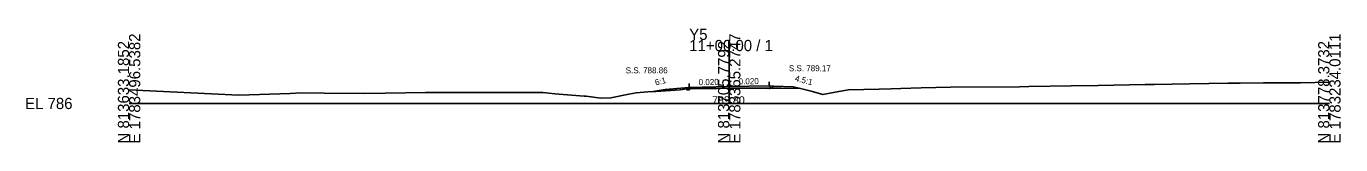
# Model space of a CAD drawing. Extents: x -26 to 1603, y -10 to 6526.
# Drawn here: x -25.7 to 302.8, y 1490.3 to 1518.7 of the extents above; entities that cross this region are included whole.
import ezdxf

# ---------------------------------------------------------------- set-up
doc = ezdxf.new("R2010")
doc.units = 0
for name, color, linetype in [('Exist Cross Section Cell', 7, 'Continuous'), ('Exist XS Center Line Elevation Label', 7, 'Continuous'), ('Exist XS Ground Line', 7, 'Continuous'), ('Prop XS Dump Level', 7, 'Continuous'), ('Prop XS Earthwork Shape', 7, 'Continuous'), ('Prop XS EOT Tick Mark', 7, 'Continuous'), ('Prop XS Finish Grade', 7, 'Continuous'), ('Prop XS Finish Grade Earthwork', 7, 'Continuous'), ('Prop XS Finish Grade Pavement', 7, 'Continuous'), ('Prop XS Pvmt Edge Slope', 7, 'Continuous'), ('Prop XS SE Text', 7, 'Continuous'), ('Prop XS Side Slope Text', 7, 'Continuous'), ('Prop XS SS Elevation Text', 7, 'Continuous'), ('Prop XS Subgrade Earthwork', 7, 'Continuous')]:
    doc.layers.add(name, color=color, linetype=linetype)

msp = doc.modelspace()

# ---------------------------------------------------------------- linework, layer by layer
at = {"layer": 'Exist Cross Section Cell'}
for p, q in [((150, 1500), (150, 1515.87)), ((0, 1500), (150, 1500)), ((150, 1500), (300, 1500))]:
    msp.add_line(p, q, dxfattribs=at)
at = {"layer": 'Exist XS Ground Line'}
for p, q in [((242.2, 1504.49), (253.93, 1504.73)), ((253.93, 1504.73), (256.25, 1504.77)), ((256.25, 1504.77), (265.03, 1504.9)), ((265.03, 1504.9), (274.7, 1505.08)), ((274.7, 1505.08), (277.69, 1505.08)), ((277.69, 1505.08), (283.57, 1505.13)), ((283.57, 1505.13), (292.81, 1505.19)), ((292.81, 1505.19), (300, 1505.29)), ((0, 1503.43), (27.43, 1502.11)), ((27.43, 1502.11), (40.23, 1502.53)), ((40.23, 1502.53), (43.04, 1502.62)), ((43.04, 1502.62), (48.73, 1502.57)), ((48.73, 1502.57), (58.62, 1502.5)), ((58.62, 1502.5), (64.04, 1502.59)), ((64.04, 1502.59), (74.09, 1502.72)), ((74.09, 1502.72), (83.9, 1502.73)), ((83.9, 1502.73), (89.5, 1502.72)), ((89.5, 1502.72), (91.24, 1502.7)), ((91.24, 1502.7), (103.45, 1502.75)), ((103.45, 1502.75), (106.4, 1502.4)), ((106.4, 1502.4), (113.73, 1501.86)), ((113.73, 1501.86), (114.22, 1501.82)), ((114.22, 1501.82), (117.9, 1501.35)), ((117.9, 1501.35), (120.45, 1501.42)), ((120.45, 1501.42), (124.93, 1502.32)), ((124.93, 1502.32), (126.77, 1502.68)), ((126.77, 1502.68), (129.68, 1502.88)), ((129.68, 1502.88), (137.75, 1503.43)), ((137.75, 1503.43), (139.95, 1503.73)), ((139.95, 1503.73), (146.97, 1503.76)), ((146.97, 1503.76), (149.95, 1503.8)), ((149.95, 1503.8), (153.46, 1503.8)), ((153.46, 1503.8), (159.55, 1503.83)), ((159.55, 1503.83), (163.17, 1503.79)), ((163.17, 1503.79), (167.8, 1503.76)), ((167.8, 1503.76), (170.52, 1503.04)), ((170.52, 1503.04), (173.4, 1502.24)), ((173.4, 1502.24), (177.43, 1502.95)), ((177.43, 1502.95), (179.81, 1503.44)), ((179.81, 1503.44), (187.51, 1503.6)), ((187.51, 1503.6), (190.48, 1503.66)), ((190.48, 1503.66), (192.92, 1503.72)), ((192.92, 1503.72), (197.98, 1503.9)), ((197.98, 1503.9), (205.28, 1504.08)), ((205.28, 1504.08), (222.58, 1504.18)), ((222.58, 1504.18), (224.86, 1504.2)), ((224.86, 1504.2), (235.45, 1504.39)), ((235.45, 1504.39), (242.2, 1504.49))]:
    msp.add_line(p, q, dxfattribs=at)
at = {"layer": 'Prop XS Dump Level'}
for p, q in [((140, 1504), (150, 1504.2)), ((150, 1504.2), (160, 1504.4))]:
    msp.add_line(p, q, dxfattribs=at)
at = {"layer": 'Prop XS Earthwork Shape'}
for points in [[(134, 1503.52), (130.47, 1502.93), (137.75, 1503.43), (139.19, 1503.62), (138.9, 1503.91)], [(140.04, 1503.42), (140.04, 1503.73), (139.95, 1503.73), (139.19, 1503.62), (139.4, 1503.41)], [(159.61, 1503.81), (160.26, 1503.82), (159.61, 1503.83)], [(161.1, 1504.36), (166, 1504.16), (167.8, 1503.76), (163.17, 1503.79), (160.26, 1503.82), (160.57, 1503.83)]]:
    msp.add_lwpolyline(points, close=True, dxfattribs=at)
at = {"layer": 'Prop XS EOT Tick Mark'}
for p, q in [((140, 1504), (140, 1505)), ((160, 1504.4), (160, 1505.4))]:
    msp.add_line(p, q, dxfattribs=at)
at = {"layer": 'Prop XS Finish Grade'}
for p, q in [((140, 1504), (138.9, 1503.91)), ((160, 1504.4), (161.1, 1504.36))]:
    msp.add_line(p, q, dxfattribs=at)
at = {"layer": 'Prop XS Finish Grade Earthwork'}
for p, q in [((134, 1503.52), (130.47, 1502.93)), ((138.9, 1503.91), (134, 1503.52)), ((161.1, 1504.36), (166, 1504.16)), ((166, 1504.16), (167.8, 1503.76))]:
    msp.add_line(p, q, dxfattribs=at)
at = {"layer": 'Prop XS Finish Grade Pavement'}
for p, q in [((140, 1504), (150, 1504.2)), ((150, 1504.2), (160, 1504.4))]:
    msp.add_line(p, q, dxfattribs=at)
at = {"layer": 'Prop XS Pvmt Edge Slope'}
for p, q in [((140, 1504), (139.4, 1503.41)), ((160, 1504.4), (160.57, 1503.83))]:
    msp.add_line(p, q, dxfattribs=at)
at = {"layer": 'Prop XS Subgrade Earthwork'}
for p, q in [((139.4, 1503.41), (138.9, 1503.91)), ((139.4, 1503.41), (140.04, 1503.42)), ((140.04, 1503.42), (140.04, 1503.73)), ((159.61, 1503.83), (159.61, 1503.81)), ((159.61, 1503.81), (160.57, 1503.83)), ((160.57, 1503.83), (161.1, 1504.36))]:
    msp.add_line(p, q, dxfattribs=at)

# ---------------------------------------------------------------- texts
at = {"layer": 'Exist Cross Section Cell'}
for s, p in [('Y5', (140, 1515.87)), ('11+00.00 / 1', (140, 1513.07)), ('EL 786', (-26, 1498.6))]:
    msp.add_text(s, height=2.8, dxfattribs=at).set_placement(p)
for s, p in [('N 813633.1852', (0, 1490)), ('E 1783496.5382', (2.8, 1490)), ('N 813705.7792', (150, 1490)), ('E 1783365.2747', (152.8, 1490)), ('N 813778.3732', (300, 1490)), ('E 1783234.0111', (302.8, 1490))]:
    msp.add_text(s, height=2.8, rotation=90, dxfattribs=at).set_placement(p)
at = {"layer": 'Exist XS Center Line Elevation Label'}
msp.add_text('789.80', height=2, dxfattribs=at).set_placement((145.71, 1499.8))
at = {"layer": 'Prop XS Dump Level'}
for s, height, p in [('Case1', 0.04, (134, 1503.48)), ('Eop', 0.3, (140.04, 1503.43)), ('Eop', 0.3, (159.61, 1503.53)), ('Case1', 0.04, (166, 1504.12))]:
    msp.add_text(s, height=height, dxfattribs=at).set_placement(p)
at = {"layer": 'Prop XS SE Text'}
for p in [(142.38, 1504.55), (152.38, 1504.75)]:
    msp.add_text('0.020', height=1.5, rotation=1.1458, dxfattribs=at).set_placement(p)
at = {"layer": 'Prop XS Side Slope Text'}
for s, rotation, p in [('6:1', 14.0362, (131.64, 1504.48)), ('4.5:1', 345.9638, (166.32, 1505.63))]:
    msp.add_text(s, height=1.5, rotation=rotation, dxfattribs=at).set_placement(p)
at = {"layer": 'Prop XS SS Elevation Text'}
for s, p in [('S.S. 788.86', (124.13, 1507.53)), ('S.S. 789.17', (164.91, 1508.06))]:
    msp.add_text(s, height=1.5, dxfattribs=at).set_placement(p)

doc.saveas('drawing.dxf')
